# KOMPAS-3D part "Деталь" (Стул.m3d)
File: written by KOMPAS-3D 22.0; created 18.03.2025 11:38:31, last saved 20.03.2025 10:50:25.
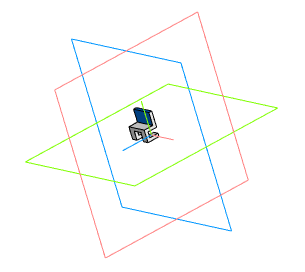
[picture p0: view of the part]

Document properties: Автор: Пользователь Windows; Полное имя файла: C:\Users\Student\Documents\Картошечка\База Сабнатика\Мебель\Стул.m3d

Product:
- Part/product: Деталь
    Масса: 0.000607

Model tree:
1. Эскиз:1
2. Эскиз:2
3. Элемент по траектории:1
4. Элемент выдавливания:1  (with: Элемент по траектории:1)
     Расстояние 1 = 2
5. Эскиз:3  (with: Элемент по траектории:1, Элемент выдавливания:1)
6. Элемент выдавливания:2  (with: Элемент по траектории:1)
     Расстояние 1 = 3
